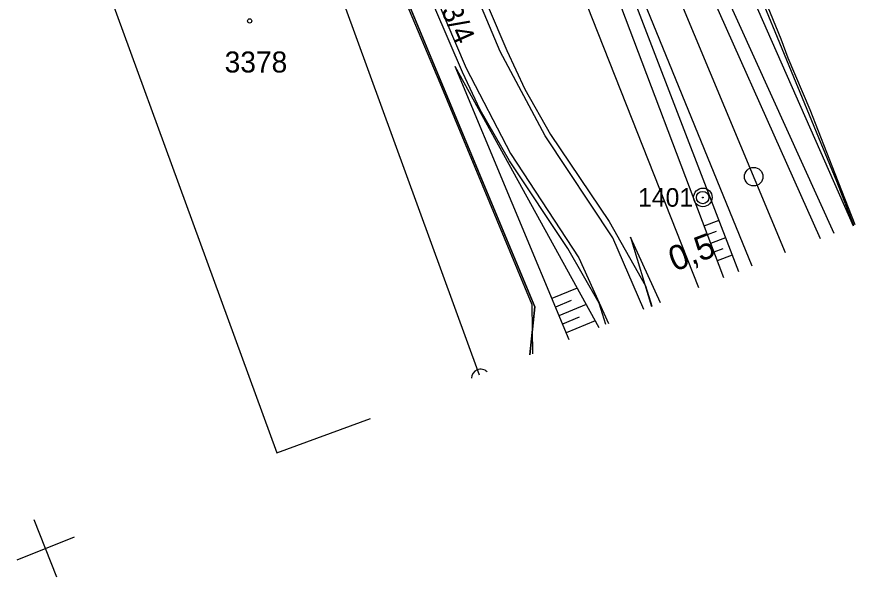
# Model space of a CAD drawing. Extents: x -834059 to -833839, y -1109191 to -1108937.
# Drawn here: x -833981.2 to -833913.5, y -1109191.3 to -1109146 of the extents above; entities that cross this region are included whole.
import ezdxf

# ---------------------------------------------------------------- set-up
doc = ezdxf.new("R2010")
doc.units = 0
for name, color, linetype in [('230_sdělovací vedení (DOK) _SŽ_SSZT_zákres', 7, 'Continuous'), ('Hranice parcel', 7, 'Continuous'), ('Parcelní čísla', 7, 'Continuous'), ('Vrstva 1', 7, 'Continuous'), ('Vrstva 17', 7, 'Continuous'), ('Vrstva 32', 7, 'Continuous'), ('Vrstva 48', 7, 'Continuous'), ('Vrstva 49', 7, 'Continuous'), ('Vrstva 51', 7, 'Continuous'), ('Vrstva 53', 7, 'Continuous'), ('Vrstva 60', 7, 'Continuous'), ('Vrstva 7', 7, 'Continuous'), ('Značky bodu BP', 7, 'Continuous'), ('Značky budov', 7, 'Continuous')]:
    doc.layers.add(name, color=color, linetype=linetype)

msp = doc.modelspace()

# ---------------------------------------------------------------- linework, layer by layer
at = {"layer": '230_sdělovací vedení (DOK) _SŽ_SSZT_zákres'}
msp.add_lwpolyline([(-833913.455, -1109162.854), (-833915.078, -1109158.715), (-833917.108, -1109153.542), (-833918.881, -1109149.364), (-833919.442, -1109147.827), (-833920.735, -1109144.687)], dxfattribs=at)
at = {"layer": 'Hranice parcel'}
for points in [[(-833933.615, -1109170.912), (-833934.16, -1109169.17), (-833936.69, -1109164.77), (-833941.39, -1109157.67), (-833943.78, -1109153.55), (-833945.19, -1109150.49), (-833958.77, -1109118.89), (-833959.28, -1109117.3), (-833959.51, -1109115.81), (-833959.48, -1109113.97), (-833959.21, -1109112.49), (-833958.71, -1109111.08), (-833958.02, -1109109.75), (-833957.13, -1109108.54), (-833956.07, -1109107.48), (-833954.73, -1109106.5), (-833953.39, -1109105.82), (-833951.04, -1109104.84)], [(-833949.57, -1109108.56), (-833951.3, -1109109.28), (-833952.61, -1109110.01), (-833953.72, -1109111.02), (-833954.69, -1109113.06), (-833954.66, -1109114.76), (-833954.48, -1109116.09), (-833953.5, -1109120.33), (-833950.59, -1109127.73), (-833941.63, -1109148.75), (-833940.17, -1109151.88), (-833938.09, -1109155.54), (-833933.34, -1109162.57), (-833930.4, -1109167.78), (-833929.899, -1109169.427)], [(-833949.57, -1109108.56), (-833926.128, -1109167.92)], [(-833962.48, -1109113.89), (-833941.85, -1109163.47), (-833939.35, -1109169.47), (-833939.75, -1109173.365)], [(-833943.83, -1109174.996), (-833964.59, -1109117.98), (-833981.08, -1109124.05), (-833960.22, -1109181.28)], [(-833960.22, -1109181.28), (-833952.646, -1109178.519)]]:
    msp.add_lwpolyline(points, dxfattribs=at)
at = {"layer": 'Vrstva 1'}
msp.add_lwpolyline([(-833919.095, -1109165.109), (-833936.116, -1109124.27), (-833943.507, -1109106.495), (-833945.392, -1109101.976), (-833955.353, -1109078.124), (-833959.494, -1109068.179)], dxfattribs=at)
at = {"layer": 'Vrstva 17'}
for points in [[(-833962.374, -1109115.013), (-833947.045, -1109151.363), (-833939.589, -1109169.287)], [(-833939.589, -1109169.287), (-833939.556, -1109173.287)]]:
    msp.add_lwpolyline(points, dxfattribs=at)
at = {"layer": 'Vrstva 32'}
msp.add_lwpolyline([(-833913.581, -1109162.904), (-833914.944, -1109159.355), (-833925.427, -1109133.873), (-833930.223, -1109122.803), (-833933.846, -1109112.792), (-833937.144, -1109103.273), (-833938.97, -1109099.834), (-833943.29, -1109094.685), (-833946.605, -1109088.611), (-833951.025, -1109077.511), (-833954.24, -1109069.999), (-833955.841, -1109066.719)], dxfattribs=at)
msp.add_lwpolyline([(-833913.581, -1109162.904), (-833914.944, -1109159.355), (-833925.427, -1109133.873), (-833930.223, -1109122.803), (-833933.846, -1109112.792), (-833937.144, -1109103.273), (-833938.97, -1109099.834), (-833943.29, -1109094.685), (-833946.605, -1109088.611), (-833951.025, -1109077.511), (-833954.24, -1109069.999), (-833955.841, -1109066.719)], dxfattribs=at)
msp.add_lwpolyline([(-833913.581, -1109162.904), (-833914.944, -1109159.355), (-833925.427, -1109133.873), (-833930.223, -1109122.803), (-833933.846, -1109112.792), (-833937.144, -1109103.273), (-833938.97, -1109099.834), (-833943.29, -1109094.685), (-833946.605, -1109088.611), (-833951.025, -1109077.511), (-833954.24, -1109069.999), (-833955.841, -1109066.719)], dxfattribs=at)
at = {"layer": 'Vrstva 48'}
for p, q in [((-833924.473, -1109162.496), (-833925.688, -1109162.955)), ((-833924.691, -1109163.38), (-833925.423, -1109163.656)), ((-833923.934, -1109163.896), (-833925.158, -1109164.358)), ((-833924.156, -1109164.781), (-833924.893, -1109165.059)), ((-833923.396, -1109165.296), (-833924.628, -1109165.761)), ((-833935.944, -1109167.962), (-833937.984, -1109168.812)), ((-833936.426, -1109168.976), (-833937.695, -1109169.504)), ((-833935.217, -1109169.285), (-833937.407, -1109170.197)), ((-833935.759, -1109170.323), (-833937.119, -1109170.889)), ((-833934.49, -1109170.606), (-833936.83, -1109171.581))]:
    msp.add_line(p, q, dxfattribs=at)
at = {"layer": 'Vrstva 49'}
for points in [[(-833938.208, -1109106.483), (-833925.197, -1109136.624), (-833913.625, -1109162.922)], [(-833915.163, -1109163.537), (-833926.641, -1109138.224)], [(-833916.266, -1109163.978), (-833927.619, -1109138.553)], [(-833921.773, -1109166.179), (-833932.091, -1109140.953)], [(-833933.788, -1109141.516), (-833924.116, -1109167.115)], [(-833932.672, -1109141.184), (-833922.885, -1109166.623)], [(-833945.812, -1109150.016), (-833934.194, -1109171.144)], [(-833945.812, -1109150.016), (-833936.61, -1109172.11)], [(-833931.628, -1109163.841), (-833929.931, -1109169.44)], [(-833929.189, -1109169.143), (-833931.628, -1109163.841)]]:
    msp.add_lwpolyline(points, dxfattribs=at)
at = {"layer": 'Vrstva 51'}
for points in [[(-833930.545, -1109169.685), (-833933.039, -1109163.901), (-833938.514, -1109155.663), (-833942.151, -1109148.838), (-833952.19, -1109125.014), (-833954.787, -1109117.285), (-833955.02, -1109112.61), (-833952.968, -1109110.021), (-833946.366, -1109106.694)], [(-833969.284, -1109113.442), (-833959.261, -1109112.507), (-833957.939, -1109118.413), (-833955.134, -1109126.136), (-833944.916, -1109150.188), (-833941.317, -1109157.071), (-833935.792, -1109165.52), (-833933.391, -1109170.823)]]:
    msp.add_lwpolyline(points, dxfattribs=at)
at = {"layer": 'Vrstva 53'}
msp.add_lwpolyline([(-833939.75, -1109173.365), (-833939.35, -1109169.47), (-833962.48, -1109113.89), (-833963.97, -1109110.49), (-833965.53, -1109106.68)], dxfattribs=at)
at = {"layer": 'Vrstva 60'}
for p, q in [((-833977.984, -1109191.34), (-833979.84, -1109186.697)), ((-833976.591, -1109188.091), (-833981.233, -1109189.947))]:
    msp.add_line(p, q, dxfattribs=at)
at = {"layer": 'Vrstva 7'}
msp.add_line((-833925.835, -1109160.64), (-833925.735, -1109160.64), dxfattribs=at)
for centre, radius in [((-833921.662, -1109158.951), 0.75), ((-833925.785, -1109160.64), 0.5)]:
    msp.add_circle(centre, radius, dxfattribs=at)
at = {"layer": 'Značky bodu BP'}
for radius in [0.75, 0.03]:
    msp.add_circle((-833925.77, -1109160.63), radius, dxfattribs=at)
msp.add_arc((-833943.73, -1109175.27), 0.75, 44.67973, 178.8958, dxfattribs=at)
at = {"layer": 'Značky budov'}
msp.add_circle((-833962.407, -1109146.359), 0.175, dxfattribs=at)

# ---------------------------------------------------------------- texts
at = {"layer": 'Parcelní čísla'}
msp.add_text('3933/4', height=1.7, rotation=294, dxfattribs=at).set_placement((-833948.511, -1109142.025))
msp.add_text('3378', height=1.7, dxfattribs=at).set_placement((-833964.427, -1109150.53))
at = {"layer": 'Vrstva 48'}
msp.add_text('0,5', height=2, rotation=21.04247, dxfattribs=at).set_placement((-833928.064, -1109166.647))
at = {"layer": 'Značky bodu BP'}
msp.add_text('1401', height=1.5, dxfattribs=at).set_placement((-833931.018, -1109161.38))

doc.saveas('drawing.dxf')
